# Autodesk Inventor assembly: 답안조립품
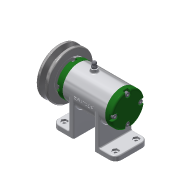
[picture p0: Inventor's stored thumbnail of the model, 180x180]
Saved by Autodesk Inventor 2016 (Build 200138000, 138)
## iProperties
Created: 2017-02
Part Number: 답안조립품
Material: 일반
Document SubType Name: Assembly
Designer: H
Author: H
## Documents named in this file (16)
- C:\Users\CAMTIC\Desktop\470207V1007\답안조립품.iam
- C:\Users\CAMTIC\Desktop\470207V1007\본체.ipt
- C:\Users\CAMTIC\Desktop\470207V1007\V벨트풀리.ipt
- C:\Users\CAMTIC\Desktop\470207V1007\너트 M 8.ipt
- C:\Users\CAMTIC\Desktop\470207V1007\니플 M 6 x 0.75.ipt
- C:\Users\CAMTIC\Desktop\470207V1007\뒤커버.ipt
- C:\Users\CAMTIC\Desktop\470207V1007\베어링 15 x 32 x 9.ipt
- C:\Users\CAMTIC\Desktop\470207V1007\볼트 M 6 x 8.ipt
- C:\Users\CAMTIC\Desktop\470207V1007\볼트 M4 x 12.ipt
- C:\Users\CAMTIC\Desktop\470207V1007\스프링와셔 8.ipt
- C:\Users\CAMTIC\Desktop\470207V1007\앞커버.ipt
- C:\Users\CAMTIC\Desktop\470207V1007\오일 실 15 25 7.ipt
- C:\Users\CAMTIC\Desktop\470207V1007\와셔 6x11.5.ipt
- C:\Users\CAMTIC\Desktop\470207V1007\와셔 8x17.ipt
- C:\Users\CAMTIC\Desktop\470207V1007\축.ipt
- C:\Users\CAMTIC\Desktop\470207V1007\키 3 x 3 x 12.ipt
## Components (11 placed, 3 different names)
1. V벨트풀리:1
2. KS B 2023 6002 - 15 x 32 x 9:1
3. KS B 2023 6002 - 15 x 32 x 9:2
4. ISO 4762 M4 x 12:1
5. ISO 4762 M4 x 12:3
6. ISO 4762 M4 x 12:4
7. ISO 4762 M4 x 12:5
8. ISO 4762 M4 x 12:2
9. ISO 4762 M4 x 12:6
10. ISO 4762 M4 x 12:7
11. ISO 4762 M4 x 12:8
